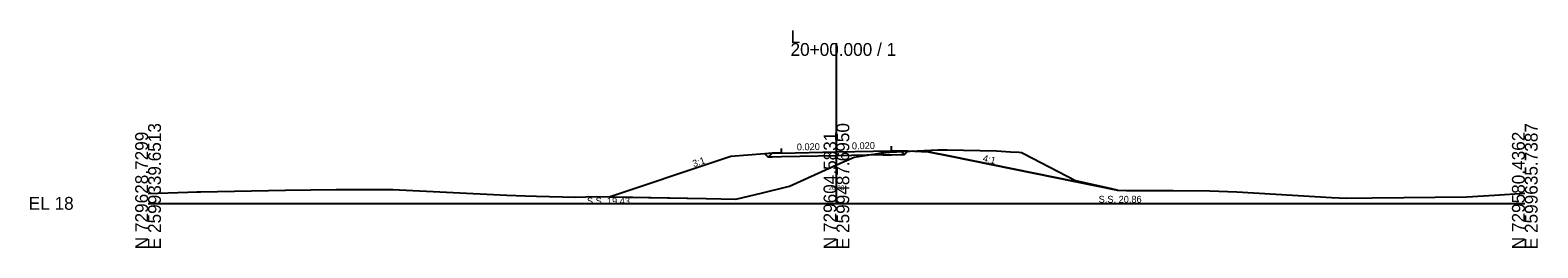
# Model space of a CAD drawing. Extents: x -26 to 3303, y -10 to 9555.
# Drawn here: x 1974.3 to 2302.8, y -9.7 to 37.7 of the extents above; entities that cross this region are included whole.
import ezdxf

# ---------------------------------------------------------------- set-up
doc = ezdxf.new("R2010")
doc.units = 0
for name, color, linetype in [('Exist Cross Section Cell', 7, 'Continuous'), ('Exist XS Center Line Elevation Label', 7, 'Continuous'), ('Exist XS Ground Line', 7, 'Continuous'), ('Prop XS Ditch Slope Text', 7, 'Continuous'), ('Prop XS Dump Level', 7, 'Continuous'), ('Prop XS Earthwork Shape', 7, 'Continuous'), ('Prop XS EOT Tick Mark', 7, 'Continuous'), ('Prop XS Finish Grade', 7, 'Continuous'), ('Prop XS Finish Grade Earthwork', 7, 'Continuous'), ('Prop XS Finish Grade Paved Shoulder', 7, 'Continuous'), ('Prop XS Finish Grade Pavement', 7, 'Continuous'), ('Prop XS Pvmt Edge Slope', 7, 'Continuous'), ('Prop XS SE Text', 7, 'Continuous'), ('Prop XS Side Slope Text', 7, 'Continuous'), ('Prop XS SS Elevation Text', 7, 'Continuous'), ('Prop XS Subgrade Earthwork', 7, 'Continuous')]:
    doc.layers.add(name, color=color, linetype=linetype)

msp = doc.modelspace()

# ---------------------------------------------------------------- linework, layer by layer
at = {"layer": 'Exist Cross Section Cell'}
for p, q in [((2150, 0), (2150, 34.92)), ((2000, 0), (2150, 0)), ((2150, 0), (2300, 0))]:
    msp.add_line(p, q, dxfattribs=at)
at = {"layer": 'Exist XS Ground Line'}
msp.add_lwpolyline([(2000, 2.14), (2008.66, 2.43), (2010.66, 2.48), (2011.4, 2.5), (2029.95, 2.87), (2041, 2.99), (2041.39, 3), (2041.99, 3), (2053.37, 3), (2078.15, 1.81), (2082.14, 1.66), (2084.64, 1.58), (2093.16, 1.36), (2097.66, 1.48), (2121.6, 1.08), (2128.08, 0.91), (2133.91, 2.26), (2139.75, 3.75), (2149.24, 8.06), (2150, 8.38), (2153.87, 10.03), (2159, 10.89), (2160.12, 11.08), (2172.07, 11.62), (2172.55, 11.64), (2173.1, 11.63), (2174.13, 11.62), (2184.86, 11.45), (2187.96, 11.22), (2189.74, 11.12), (2190.33, 11.07), (2190.77, 10.85), (2202.08, 4.99), (2209.94, 3.23), (2211.23, 2.86), (2213.14, 2.83), (2223.35, 2.78), (2231.34, 2.72), (2237.27, 2.52), (2257.85, 1.28), (2261.23, 1.16), (2266.71, 1.23), (2287.35, 1.42), (2293.43, 1.79), (2300, 2.2)], dxfattribs=at)
at = {"layer": 'Prop XS Dump Level'}
for p, q in [((2138, 10.95), (2150, 11.19)), ((2150, 11.19), (2162, 11.43))]:
    msp.add_line(p, q, dxfattribs=at)
at = {"layer": 'Prop XS Earthwork Shape'}
for points in [[(2135.15, 10.06), (2134.43, 10.78), (2127, 10.19), (2123.91, 9.16), (2100.73, 1.43), (2121.6, 1.08), (2128.08, 0.91), (2133.91, 2.26), (2139.75, 3.75), (2149.24, 8.06), (2150, 8.38), (2153.87, 10.03), (2156.61, 10.49), (2150, 10.36), (2138, 10.12), (2136, 10.08)], [(2128.08, 0.91), (2133.91, 2.26), (2139.75, 3.75), (2149.24, 8.06), (2150, 8.38), (2153.87, 10.03), (2156.61, 10.49), (2150, 10.36), (2138, 10.12), (2136, 10.08), (2135.15, 10.06), (2134.43, 10.78), (2127, 10.19), (2123.91, 9.16), (2100.73, 1.43), (2121.6, 1.08)], [(2159, 10.89), (2160.12, 11.08), (2160.12, 10.56), (2156.61, 10.49)], [(2156.61, 10.49), (2159, 10.89), (2160.12, 11.08), (2160.12, 10.56)], [(2162, 10.6), (2164, 10.64), (2164.82, 10.65), (2165.49, 11.32), (2160.12, 11.08), (2160.12, 10.56)], [(2162, 10.6), (2164, 10.64), (2164.82, 10.65), (2165.49, 11.32), (2160.12, 11.08), (2160.12, 10.56)], [(2165.57, 11.41), (2166.51, 11.37), (2165.49, 11.32)], [(2165.49, 11.32), (2165.57, 11.41), (2166.51, 11.37)], [(2173.1, 11.63), (2174.13, 11.62), (2184.86, 11.45), (2187.96, 11.22), (2189.74, 11.12), (2190.33, 11.07), (2190.77, 10.85), (2202.08, 4.99), (2209.94, 3.23), (2211.23, 2.86), (2174.81, 10.25), (2170, 11.23), (2166.51, 11.37), (2172.07, 11.62), (2172.55, 11.64)], [(2172.55, 11.64), (2173.1, 11.63), (2174.13, 11.62), (2184.86, 11.45), (2187.96, 11.22), (2189.74, 11.12), (2190.33, 11.07), (2190.77, 10.85), (2202.08, 4.99), (2209.94, 3.23), (2211.23, 2.86), (2174.81, 10.25), (2170, 11.23), (2166.51, 11.37), (2172.07, 11.62)]]:
    msp.add_lwpolyline(points, close=True, dxfattribs=at)
at = {"layer": 'Prop XS EOT Tick Mark'}
for p, q in [((2138, 10.95), (2138, 11.95)), ((2162, 11.43), (2162, 12.43))]:
    msp.add_line(p, q, dxfattribs=at)
at = {"layer": 'Prop XS Finish Grade'}
for p, q in [((2136, 10.91), (2134.43, 10.78)), ((2164, 11.47), (2165.57, 11.41))]:
    msp.add_line(p, q, dxfattribs=at)
at = {"layer": 'Prop XS Finish Grade Earthwork'}
for p, q in [((2127, 10.19), (2123.91, 9.16)), ((2134.43, 10.78), (2127, 10.19)), ((2165.57, 11.41), (2170, 11.23)), ((2170, 11.23), (2174.81, 10.25)), ((2174.81, 10.25), (2211.23, 2.86)), ((2123.91, 9.16), (2100.73, 1.43))]:
    msp.add_line(p, q, dxfattribs=at)
at = {"layer": 'Prop XS Finish Grade Paved Shoulder'}
for p, q in [((2138, 10.95), (2136, 10.91)), ((2162, 11.43), (2164, 11.47))]:
    msp.add_line(p, q, dxfattribs=at)
at = {"layer": 'Prop XS Finish Grade Pavement'}
for p, q in [((2138, 10.95), (2150, 11.19)), ((2150, 11.19), (2162, 11.43))]:
    msp.add_line(p, q, dxfattribs=at)
at = {"layer": 'Prop XS Pvmt Edge Slope'}
for p, q in [((2135.15, 10.06), (2134.43, 10.78)), ((2136, 10.91), (2135.15, 10.06)), ((2164, 11.47), (2164.82, 10.65)), ((2164.82, 10.65), (2165.57, 11.41))]:
    msp.add_line(p, q, dxfattribs=at)
at = {"layer": 'Prop XS Subgrade Earthwork'}
for p, q in [((2135.15, 10.06), (2134.43, 10.78)), ((2136, 10.08), (2135.15, 10.06)), ((2138, 10.12), (2136, 10.08)), ((2150, 10.36), (2138, 10.12)), ((2160.12, 10.56), (2150, 10.36)), ((2160.12, 10.56), (2160.12, 11.08)), ((2160.12, 10.56), (2160.12, 11.08)), ((2160.12, 10.56), (2162, 10.6)), ((2162, 10.6), (2164, 10.64)), ((2164, 10.64), (2164.82, 10.65)), ((2164.82, 10.65), (2165.57, 11.41))]:
    msp.add_line(p, q, dxfattribs=at)

# ---------------------------------------------------------------- texts
at = {"layer": 'Exist Cross Section Cell'}
for s, p in [('L', (2140, 34.92)), ('20+00.000 / 1', (2140, 32.12)), ('EL 18', (1974, -1.4))]:
    msp.add_text(s, height=2.8, dxfattribs=at).set_placement(p)
for s, p in [('E 2599339.6513', (2002.8, -10)), ('E 2599487.6950', (2152.8, -10)), ('E 2599635.7387', (2302.8, -10)), ('N 729628.7299', (2000, -10)), ('N 729604.5831', (2150, -10)), ('N 729580.4362', (2300, -10))]:
    msp.add_text(s, height=2.8, rotation=90, dxfattribs=at).set_placement(p)
at = {"layer": 'Exist XS Center Line Elevation Label'}
msp.add_text('26.38', height=1, dxfattribs=at).set_placement((2148.26, 2.88))
at = {"layer": 'Prop XS Ditch Slope Text'}
msp.add_text('4:1', height=1.5, rotation=347.1415, dxfattribs=at).set_placement((2181.8, 9.15))
at = {"layer": 'Prop XS Dump Level'}
for s, height, p in [('Case1', 0.04, (2130, 10.39)), ('Eop', 0.3, (2160.12, 10.78)), ('Eop', 0.3, (2160.12, 10.78)), ('Case1', 0.04, (2170, 11.19))]:
    msp.add_text(s, height=height, dxfattribs=at).set_placement(p)
at = {"layer": 'Prop XS SE Text'}
for p in [(2153.38, 11.76), (2141.38, 11.52)]:
    msp.add_text('0.020', height=1.5, rotation=1.1458, dxfattribs=at).set_placement(p)
at = {"layer": 'Prop XS Side Slope Text'}
msp.add_text('3:1', height=1.5, rotation=18.4349, dxfattribs=at).set_placement((2118.91, 7.86))
at = {"layer": 'Prop XS SS Elevation Text'}
for s, p in [('S.S. 19.43', (2095.64, -0.24)), ('S.S. 20.86', (2207.14, 0.13))]:
    msp.add_text(s, height=1.5, dxfattribs=at).set_placement(p)

doc.saveas('drawing.dxf')
